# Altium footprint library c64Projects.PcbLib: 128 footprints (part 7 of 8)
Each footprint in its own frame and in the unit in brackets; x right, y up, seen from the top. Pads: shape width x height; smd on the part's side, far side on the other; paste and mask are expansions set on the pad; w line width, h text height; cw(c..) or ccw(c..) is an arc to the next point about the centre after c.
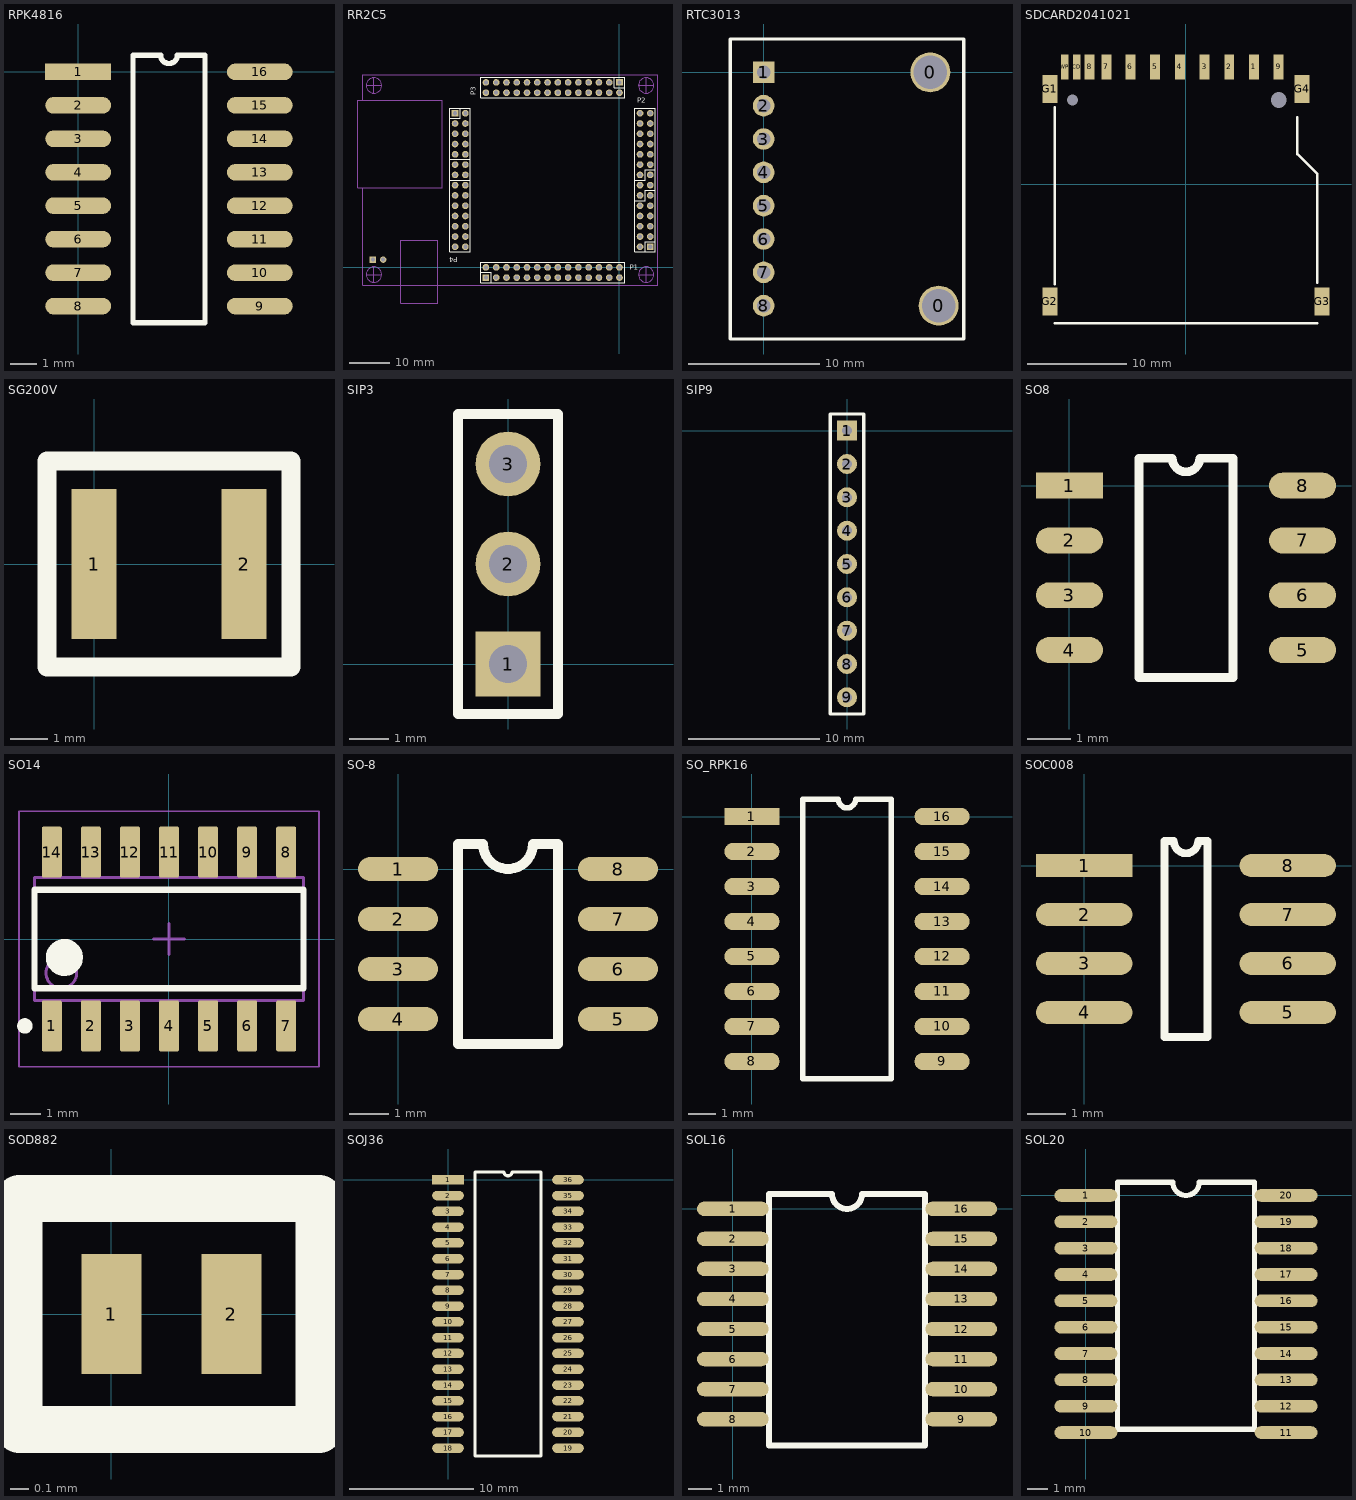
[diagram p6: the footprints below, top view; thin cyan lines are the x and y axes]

## RPK4816 [mm]
pads (16):
  rect 2.5x0.63 smd: 1(0,0)
  oval 2.5x0.63 smd: 2(0,-1.27) 3(0,-2.54) 4(0,-3.81) 5(0,-5.08) 6(0,-6.35) 7(0,-7.62) 8(0,-8.89) 9(6.9,-8.89) 10(6.9,-7.62) 11(6.9,-6.35) 12(6.9,-5.08) 13(6.9,-3.81) 14(6.9,-2.54) 15(6.9,-1.27) 16(6.9,0)
Top Overlay:
  lines w0.2: 2.085,-9.525 4.815,-9.525 4.815,0.635 3.767,0.635 cw(c3.45,0.635) 3.132,0.635 2.085,0.635 2.085,-9.525

## RR2C5 [mil]
pads (114):
  rect 62x62 hole 40 mask+10: 1(-2400,75)
  round 62 hole 40 mask+10: 2(-2300,75)
  rect 65x65 hole 40: A1(-1300,-100) B1(300,200) C1(0,1800) D1(-1600,1500)
  round 65 hole 40: A2(-1300,0) A3(-1200,-100) A4(-1200,0) A5(-1100,-100) A6(-1100,0) A7(-1000,-100) A8(-1000,0) A9(-900,-100) A10(-900,0) A11(-800,-100) A12(-800,0) A13(-700,-100) A14(-700,0) A15(-600,-100) A16(-600,0) A17(-500,-100) A18(-500,0) A19(-400,-100) A20(-400,0) A21(-300,-100) A22(-300,0) A23(-200,-100) A24(-200,0) A25(-100,-100) A26(-100,0) A27(0,-100) A28(0,0) B2(200,200) B3(300,300) B4(200,300) B5(300,400) B6(200,400) B7(300,500) B8(200,500) B9(300,600) B10(200,600) B11(300,700) B12(200,700) B13(300,800) B14(200,800) B15(300,900) B16(200,900) B17(300,1000) B18(200,1000) B19(300,1100) B20(200,1100) B21(300,1200) B22(200,1200) B23(300,1300) B24(200,1300) B25(300,1400) B26(200,1400) B27(300,1500) B28(200,1500) C2(0,1700) C3(-100,1800) C4(-100,1700) C5(-200,1800) C6(-200,1700) C7(-300,1800) C8(-300,1700) C9(-400,1800) C10(-400,1700) C11(-500,1800) C12(-500,1700) C13(-600,1800) C14(-600,1700) C15(-700,1800) C16(-700,1700) C17(-800,1800) C18(-800,1700) C19(-900,1800) C20(-900,1700) C21(-1000,1800) C22(-1000,1700) C23(-1100,1800) C24(-1100,1700) C25(-1200,1800) C26(-1200,1700) C27(-1300,1800) C28(-1300,1700) D2(-1500,1500) D3(-1600,1400) D4(-1500,1400) D5(-1600,1300) D6(-1500,1300) D7(-1600,1200) D8(-1500,1200) D9(-1600,1100) D10(-1500,1100) D11(-1600,1000) D12(-1500,1000) D13(-1600,900) D14(-1500,900) D15(-1600,800) D16(-1500,800) D17(-1600,700) D18(-1500,700) D19(-1600,600) D20(-1500,600) D21(-1600,500) D22(-1500,500) D23(-1600,400) D24(-1500,400) D25(-1600,300) D26(-1500,300) D27(-1600,200) D28(-1500,200)
Top Overlay:
  lines w10: -1650,850 -1450,850 ; -1650,1050 -1450,1050 ; -1650,1450 -1550,1450 -1550,1550 ; -1350,-50 -1250,-50 -1250,-150 ; -50,1850 -50,1750 50,1750 ; 150,650 250,650 250,750 350,750 ; 150,850 250,850 250,950 350,950 ; 250,150 250,250 350,250 ; -1650,150 -1650,1550 -1450,1550 -1450,150 -1650,150 ; -1350,-150 -1350,50 50,50 50,-150 -1350,-150 ; -1350,1650 50,1650 50,1850 -1350,1850 -1350,1650 ; 150,150 150,1550 350,1550 350,150 150,150
  text "P4" at -1575,100 h50
  text "P3" at -1400,1675 h50
  text "P2" at 175,1600 h50
  text "P1" at 100,-25 h50
Mechanical 3:
  circle w10: c-2390,-70 r75
  circle w10: c-2390,1770 r75
  circle w10: c260,1770 r75
  circle w10: c260,-70 r75
  lines w10: -2500,775 -2500,-175 375,-175 375,1875 -2500,1875 -2500,1625 -1725,1625 ; -2465,-70 -2315,-70 ; -2465,1770 -2315,1770 ; -2390,-145 -2390,5 ; -2390,1695 -2390,1845 ; -2130,-180 -2130,-350 -1770,-350 -1770,-175 -1770,265 -2130,265 -2130,-175 ; -1725,800 -1725,1575 ; 185,-70 335,-70 ; 185,1770 335,1770 ; 260,-145 260,5 ; 260,1695 260,1845 ; -1725,1625 -1725,775 -2545,775 -2545,1625 -1725,1625

## RTC3013 [mil]
pads (10):
  round 120 hole 100: 0(500,0) 0(525,-700)
  rect 65x65 hole 40: 1(0,0)
  round 65 hole 40: 2(0,-100) 3(0,-200) 4(0,-300) 5(0,-400) 6(0,-500) 7(0,-600) 8(0,-700)
Top Overlay:
  lines w10: -100,-800 -100,100 600,100 600,-800 -100,-800

## SDCARD2041021 [mm]
pads (17):
  rect 1x2.5 smd: 1(6.875,11.863) 2(4.375,11.863) 3(1.875,11.863) 4(-0.625,11.863) 5(-3.125,11.863) 6(-5.625,11.863) 7(-8.055,11.863) 8(-9.755,11.863) 9(9.375,11.863)
  rect 0.75x2.5 smd: CD(-11.055,11.863) WP(-12.255,11.863)
  rect 1.5x2.8 smd: G1(-13.775,9.638) G2(-13.775,-11.862) G3(13.775,-11.862) G4(11.75,9.638)
  round 0.5 hole 1.1 unplated: H(-11.5,8.513)
  round 0.5 hole 1.6 unplated: H(9.375,8.513)
Top Overlay:
  lines w0.254: -13.3,-14.087 13.3,-14.087 ; -13.3,-10.112 -13.3,7.763 ; 11.275,6.763 11.275,3.038 13.3,1.013 13.3,-9.987

## SG200V [mm]
pads (2):
  rect 1.2x4 smd: 1(0,0) 2(4,0)
Top Overlay:
  lines w0.508: -1.25,-2.75 -1.25,2.75 5.25,2.75 5.25,-2.75 -1.25,-2.75

## SIP3 [mil]
pads (3):
  rect 65x65 hole 38: 1(0,0)
  round 65 hole 38: 2(0,100) 3(0,200)
Top Overlay:
  lines w10: -50,-50 50,-50 50,250 -50,250 -50,-50

## SIP9 [mil]
pads (9):
  rect 60x60 hole 30: 1(0,0)
  round 60 hole 30: 2(0,-100) 3(0,-200) 4(0,-300) 5(0,-400) 6(0,-500) 7(0,-600) 8(0,-700) 9(0,-800)
Top Overlay:
  lines w10: -50,-850 -50,50 50,50 50,-850 -50,-850

## SO8 [mm]
pads (8):
  rect 1.55x0.6 smd: 1(0,0)
  oval 1.55x0.6 smd: 2(0,-1.27) 3(0,-2.54) 4(0,-3.81) 5(5.4,-3.81) 6(5.4,-2.54) 7(5.4,-1.27) 8(5.4,0)
Top Overlay:
  lines w0.2: 1.61,-4.445 3.79,-4.445 3.79,0.635 3.017,0.635 cw(c2.7,0.635) 2.382,0.635 1.61,0.635 1.61,-4.445

## SO14 [mm]
pads (14):
  rrect15% 0.65x1.65 smd: 1(-3.81,-2.825) 2(-2.54,-2.825) 3(-1.27,-2.825) 4(0,-2.825) 5(1.27,-2.825) 6(2.54,-2.825) 7(3.81,-2.825) 8(3.81,2.825) 9(2.54,2.825) 10(1.27,2.825) 11(0,2.825) 12(-1.27,2.825) 13(-2.54,2.825) 14(-3.81,2.825)
Top Overlay:
  circle w0.6: c-3.4,-0.6 r0.3
  circle w0.25: c-4.685,-2.825 r0.125
  lines w0.2: -4.375,-1.6 -4.375,1.6 4.375,1.6 4.375,-1.6 -4.375,-1.6
Outline:
3D Top:
  circle w0.1: c-3.5,-1.1 r0.5
  lines w0.1: -4.375,-2 -4.375,2 4.375,2 4.375,-2 -4.375,-2
Courtyard Top:
  lines w0.05: -4.875,-4.15 -4.875,4.15 4.875,4.15 4.875,-4.15 -4.875,-4.15
  lines w0.1: -0.5,0 0.5,0 ; 0,-0.5 0,0.5
3D body: height 1.59, standoff -0.01, extent -4.318,-3.023 4.318,3.022

## SO-8 [mil]
pads (8):
  oval 80x24 smd: 1(0,0) 2(0,-50) 3(0,-100) 4(0,-150) 5(220,-150) 6(220,-100) 7(220,-50) 8(220,0)
Top Overlay:
  lines w10: 60,-175 160,-175 160,25 135,25 cw(c110,25) 85,25 60,25 60,-175

## SO_RPK16 [mm]
pads (16):
  rect 2x0.63 smd: 1(0,0)
  oval 2x0.63 smd: 2(0,-1.27) 3(0,-2.54) 4(0,-3.81) 5(0,-5.08) 6(0,-6.35) 7(0,-7.62) 8(0,-8.89) 9(6.9,-8.89) 10(6.9,-7.62) 11(6.9,-6.35) 12(6.9,-5.08) 13(6.9,-3.81) 14(6.9,-2.54) 15(6.9,-1.27) 16(6.9,0)
Top Overlay:
  lines w0.2: 1.835,-9.525 5.065,-9.525 5.065,0.635 3.767,0.635 cw(c3.45,0.635) 3.132,0.635 1.835,0.635 1.835,-9.525

## SOC008 [mm]
pads (8):
  rect 2.5x0.6 smd: 1(0,0)
  oval 2.5x0.6 smd: 2(0,-1.27) 3(0,-2.54) 4(0,-3.81) 5(5.28,-3.81) 6(5.28,-2.54) 7(5.28,-1.27) 8(5.28,0)
Top Overlay:
  lines w0.2: 2.085,-4.445 3.195,-4.445 3.195,0.635 2.957,0.635 cw(c2.64,0.635) 2.322,0.635 2.085,0.635 2.085,-4.445

## SOD882 [mm]
pads (2):
  rect 0.325x0.65 smd: 1(0,0) 2(0.65,0)
Top Overlay:
  lines w0.254: -0.5,-0.625 -0.5,0.625 1.125,0.625 1.125,-0.625 -0.5,-0.625

## SOJ36 [mil]
pads (36):
  rect 100x30 smd: 1(0,0)
  oval 100x30 smd: 2(0,-50) 3(0,-100) 4(0,-150) 5(0,-200) 6(0,-250) 7(0,-300) 8(0,-350) 9(0,-400) 10(0,-450) 11(0,-500) 12(0,-550) 13(0,-600) 14(0,-650) 15(0,-700) 16(0,-750) 17(0,-800) 18(0,-850) 19(380,-850) 20(380,-800) 21(380,-750) 22(380,-700) 23(380,-650) 24(380,-600) 25(380,-550) 26(380,-500) 27(380,-450) 28(380,-400) 29(380,-350) 30(380,-300) 31(380,-250) 32(380,-200) 33(380,-150) 34(380,-100) 35(380,-50) 36(380,0)
Top Overlay:
  lines w10: 85,-875 295,-875 295,25 202.5,25 cw(c190,25) 177.5,25 85,25 85,-875

## SOL16 [mil]
pads (16):
  oval 119.37x24 smd: 1(0,0) 2(0,-50) 3(0,-100) 4(0,-150) 5(0,-200) 6(0,-250) 7(0,-300) 8(0,-350) 9(380,-350) 10(380,-300) 11(380,-250) 12(380,-200) 13(380,-150) 14(380,-100) 15(380,-50) 16(380,0)
Top Overlay:
  lines w10: 60,-393.7 320,-393.7 320,25 215,25 cw(c190,25) 165,25 60,25 60,-393.7

## SOL20 [mil]
pads (20):
  oval 119.37x24 smd: 1(0,0) 2(0,-50) 3(0,-100) 4(0,-150) 5(0,-200) 6(0,-250) 7(0,-300) 8(0,-350) 9(0,-400) 10(0,-450) 11(380,-450) 12(380,-400) 13(380,-350) 14(380,-300) 15(380,-250) 16(380,-200) 17(380,-150) 18(380,-100) 19(380,-50) 20(380,0)
Top Overlay:
  lines w10: 60,-443.7 320,-443.7 ; 60,-443 60,25 165,25 ccw(c190,25) 215,25 320,25 320,-443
